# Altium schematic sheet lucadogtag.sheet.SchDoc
size A4; SheetNumber: 1; SheetTotal: 1
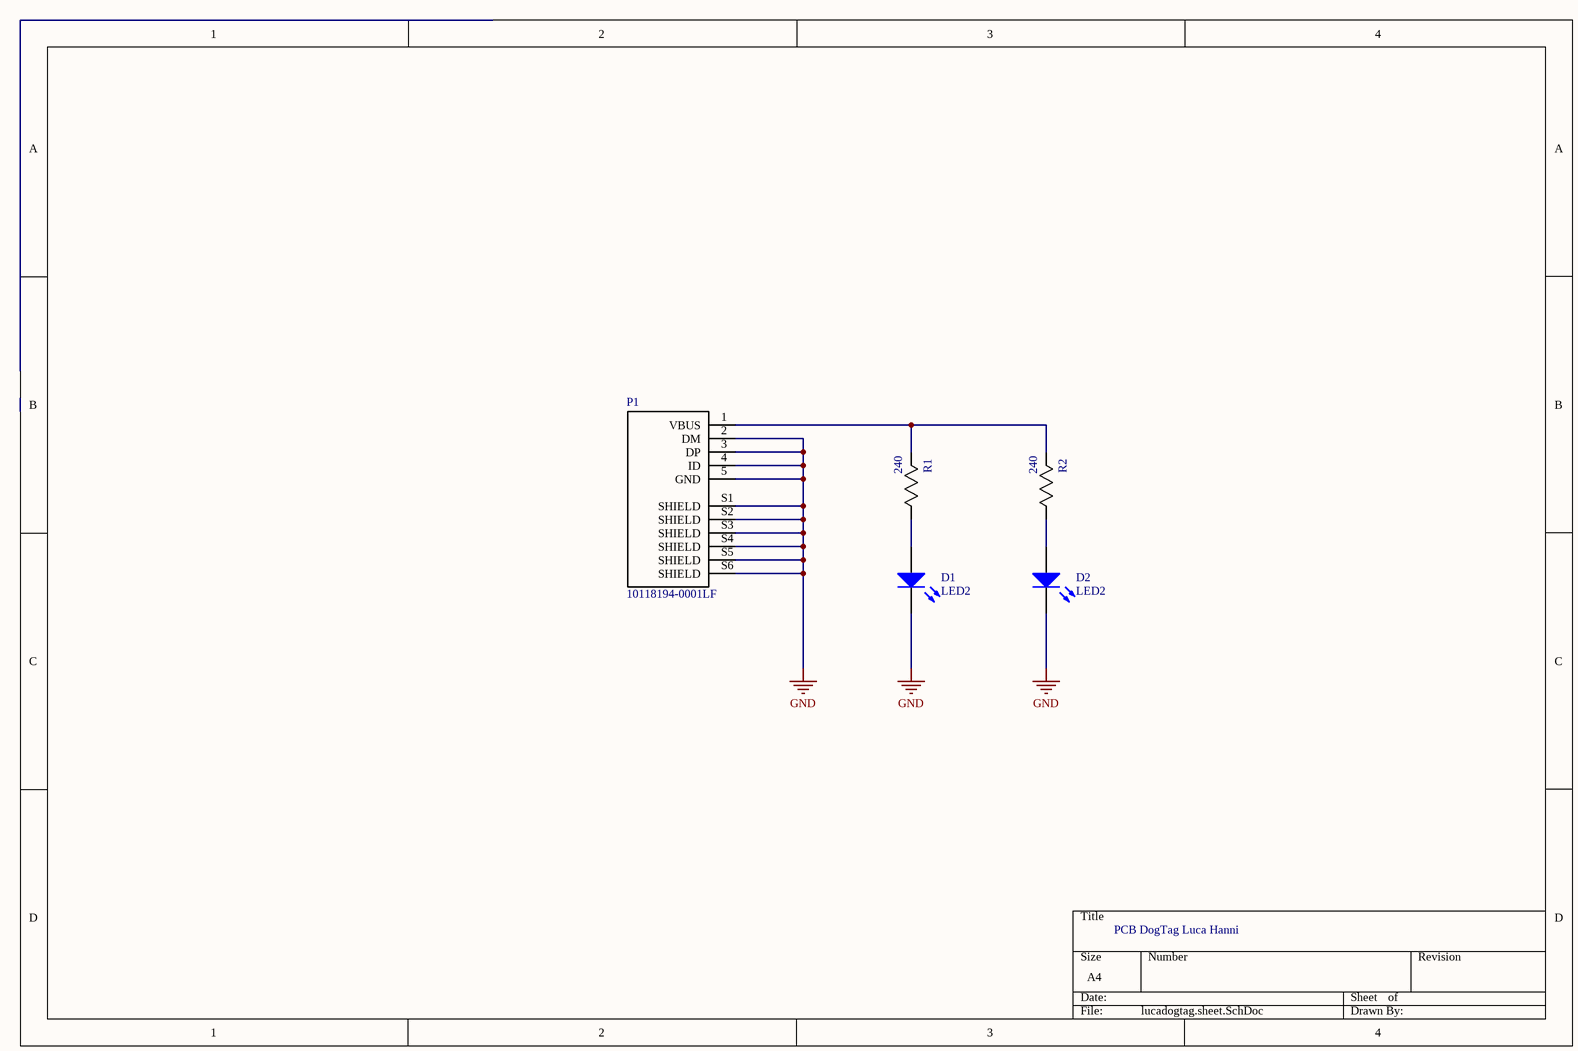
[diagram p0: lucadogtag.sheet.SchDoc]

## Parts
D1  LED2  [3.2X1.6X1.1]
D2  LED2  [3.2X1.6X1.1]
P1  10118194-0001LF  [USB Micro B Receptacle]
R1  240  [0805]
R2  240  [0805]

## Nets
GND: D1.2(K) D2.2(K) P1.2(DM) P1.3(DP) P1.4(ID) P1.5(GND) P1.S1(SHIELD) P1.S2(SHIELD) P1.S3(SHIELD) P1.S4(SHIELD) P1.S5(SHIELD) P1.S6(SHIELD)
NetD1_1: D1.1(A) R1.1(R1)
NetD2_1: D2.1(A) R2.1(R1)
NetP1_1: P1.1(VBUS) R1.2(R2) R2.2(R2)

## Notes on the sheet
- PCB DogTag Luca Hanni

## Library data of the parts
D1 D2 = LED2: Typical RED, GREEN, YELLOW, AMBER GaAs LED
P1 = USB Micro B Receptacle: USB - micro B USB 2.0 Receptacle Connector 5 Position Surface Mount, Right Angle; Through Hole; MF: Amphenol ICC (FCI); Rating: 100VAC 1.8A
R1 R2 = RES 240.0 1/8W: RES SMD 240 OHM 5% 1/8W 0805; Power (Watts): 0.125W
